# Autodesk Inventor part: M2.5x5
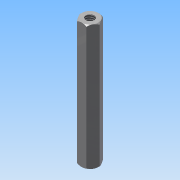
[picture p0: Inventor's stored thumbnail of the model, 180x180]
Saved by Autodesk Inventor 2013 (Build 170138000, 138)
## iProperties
Created: 2012-08
Part Number: M2.5x5
Material: Stahl
Document SubType Name: Modeling
Designer: rYan
Density: 7.85 g/cm^3
Mass: 2.5118 g
Surface Area: 6.24888 cm^2
Volume: 0.319975 cm^3
Author: rYan
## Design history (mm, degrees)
derived "Abstandsbolzen Typ A.ipt"
feature "Volumenkörper1::Abstandsbolzen Typ A.ipt"
tag "Bezeichnung1"
node "Volumenkörper1"
other parameters: "SW" = 4, "d2" = 0, "d16" = 45 deg
